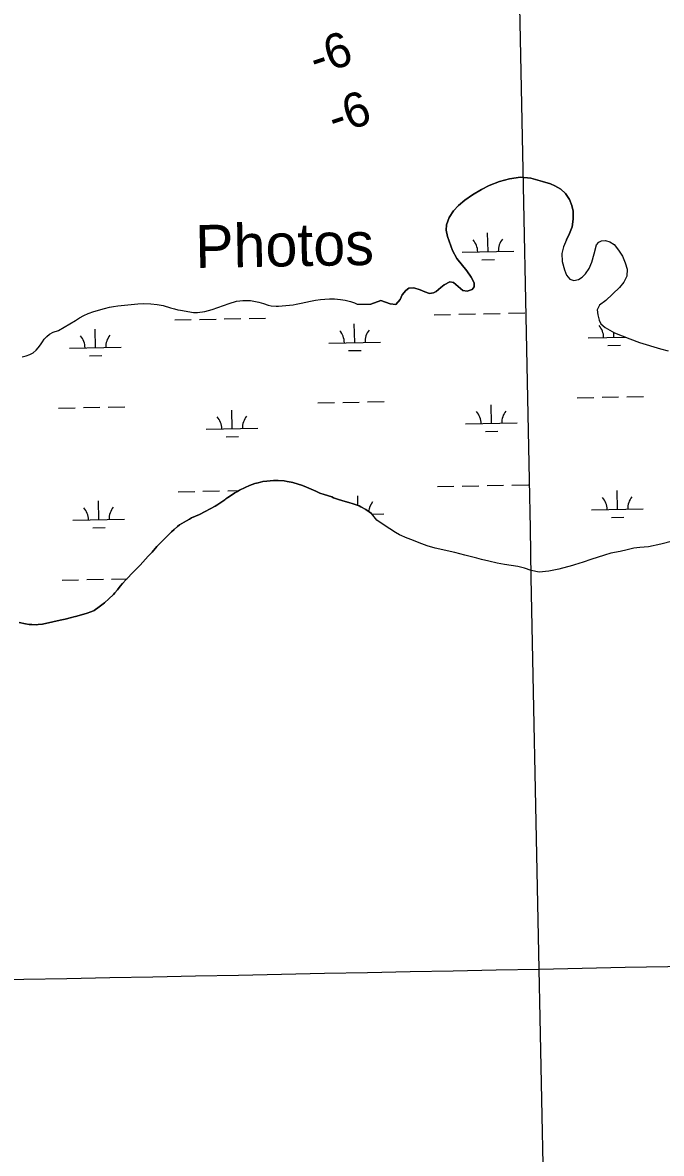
# Model space of a CAD drawing. Extents: x 3989314 to 4027622, y 243956 to 270014.
# Drawn here: x 4008451 to 4009687, y 255413 to 257601 of the extents above; entities that cross this region are included whole.
import ezdxf

# ---------------------------------------------------------------- set-up
doc = ezdxf.new("R2010")
doc.units = 0
for name, color, linetype in [('V-GRID-MAJR', 7, 'Continuous'), ('V-RIVR-EDGE', 7, 'Continuous'), ('V-RIVR-IDEN', 7, 'Continuous'), ('V-RIVR-RANG', 7, 'Continuous'), ('V-WETL-SWMP', 7, 'Continuous')]:
    doc.layers.add(name, color=color, linetype=linetype)

msp = doc.modelspace()

# ---------------------------------------------------------------- linework, layer by layer
at = {"layer": 'V-GRID-MAJR'}
for points in [[(4009571.406, 249713.95), (4009450.711, 255770.161), (4009329.948, 261829.84100000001), (4009209.185, 267889.513), (4009209.116, 267892.992)], [(3993497.629, 255455.714), (3998815.338, 255559.756), (4004133.032, 255664.571), (4009450.711, 255770.161), (4014768.3740000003, 255876.52300000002), (4020086.022, 255983.659), (4025403.6550000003, 256091.568)]]:
    msp.add_spline(points, degree=3, dxfattribs=at)
at = {"layer": 'V-RIVR-EDGE'}
for points in [[(4009503.705, 257181.21300000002), (4009509.585, 257193.147), (4009514.77, 257206.30800000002), (4009516.861, 257221.246), (4009516.791, 257236.722), (4009513.9390000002, 257247.679), (4009509.1610000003, 257258.931), (4009501.733, 257270.492), (4009493.0160000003, 257279.188), (4009480.853, 257285.557), (4009472.97, 257289.151), (4009457.146, 257294.169), (4009434.5870000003, 257300.573), (4009414.5700000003, 257302.557), (4009393.197, 257299.016), (4009373.724, 257294.21600000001), (4009353.932, 257286.522), (4009339.2090000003, 257278.45), (4009321.523, 257268.04), (4009307.23, 257258.026), (4009294.616, 257247.481), (4009285.159, 257237.335), (4009276.582, 257224.02300000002), (4009271.611, 257209.88700000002), (4009270.622, 257200), (4009273.43, 257187.351), (4009283.1040000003, 257160.252), (4009291.645, 257145.033), (4009310.5870000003, 257120.832), (4009319.211, 257108.753), (4009324.728, 257097.96600000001), (4009324.769, 257090.47100000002), (4009321.003, 257085.25), (4009311.4820000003, 257081.877), (4009303.294, 257083.063), (4009294.076, 257091.046), (4009284.8370000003, 257098.304), (4009278.105, 257099.695), (4009267.077, 257094.184), (4009260.64, 257088.552), (4009251.741, 257081.294), (4009246.113, 257078.785), (4009238.825, 257077.527), (4009229.2320000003, 257080.44400000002), (4009220.634, 257084.54200000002), (4009208.395, 257088.011), (4009198.717, 257087.786), (4009193.038, 257083.342), (4009185.792, 257074.58800000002), (4009181.923, 257065.503), (4009173.686, 257055.80800000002), (4009162.608, 257057.553), (4009144.1580000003, 257063.851), (4009125.109, 257056.861)], [(4009503.705, 257181.21300000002), (4009498.028, 257167.824), (4009494.782, 257154.854), (4009495.322, 257138.87900000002), (4009499.736, 257123.044), (4009503.568, 257112.544), (4009509.898, 257105.122), (4009517.813, 257102.734), (4009526.798, 257104.188), (4009533.935, 257108.833), (4009540.399, 257115.432), (4009547.684, 257125.63700000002), (4009552.609, 257138.078), (4009556.9, 257153.924), (4009561.966, 257171.682), (4009566.21, 257176.646), (4009571.115, 257179.176), (4009579.112, 257179.929), (4009587.755, 257177.52300000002), (4009595.828, 257171.987), (4009604.008, 257161.372), (4009611.915, 257149.555), (4009617.367, 257136.352), (4009620.918, 257124.408), (4009620.549, 257110.635), (4009614.69, 257099.429), (4009605.943, 257088.779), (4009579.8880000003, 257063.843), (4009567.3140000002, 257054.747), (4009562.72, 257045.681), (4009564.154, 257035.97100000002), (4009566.775, 257025.50400000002), (4009569.984, 257018.889), (4009578.483, 257011.168), (4009596.84, 257001.247), (4009626.028, 256989.58800000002), (4009645.185, 256982.549), (4009685.483, 256970.351), (4009700.3680000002, 256966.32700000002)], [(4008450.015, 256955.032), (4008458.166, 256956.839), (4008465.412, 256959.161), (4008471.492, 256962.26200000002), (4008477.448, 256967.691), (4008481.4620000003, 256972.215), (4008485.474, 256978.16400000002), (4008489.617, 256983.723), (4008493.115, 256988.767), (4008498.163, 256994.065), (4008503.341, 256998.331), (4008510.46, 257002.208), (4008520.421, 257005.823), (4008553.683, 257025.334), (4008561.06, 257030.24300000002), (4008569.7290000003, 257034.765), (4008578.271, 257038.511), (4008589.269, 257042.384), (4008609.7120000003, 257048.321), (4008619.415, 257050.643), (4008627.048, 257052.189), (4008635.199, 257053.478), (4008674.14, 257057.203), (4008685.654, 257057.842), (4008699.494, 257057.57200000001), (4008711.653, 257056.011), (4008723.167, 257053.803), (4008737.134, 257049.527), (4008745.023, 257047.321), (4008751.233, 257045.894), (4008756.535, 257045.114), (4008781.887, 257040.438), (4008789.907, 257040.692), (4008803.492, 257042.623), (4008817.723, 257046.494), (4008850.849, 257057.854), (4008865.339, 257062.24300000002), (4008871.4220000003, 257063.27300000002), (4008877.5, 257063.787), (4008885.004, 257064.03900000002), (4008892.119, 257063.519), (4008908.288, 257060.27300000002), (4008917.471, 257057.678), (4008926.394, 257054.82700000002), (4008932.473, 257053.4), (4008941.529, 257052.488), (4008946.573, 257052.484), (4008975.034, 257055.44), (4008980.469, 257056.859), (4008989.913, 257058.534), (4009008.543, 257062.661), (4009017.989, 257064.207), (4009027.563, 257065.622), (4009035.972, 257066.392), (4009045.287, 257066.904), (4009054.472, 257066.767), (4009066.242, 257065.725), (4009075.427, 257064.295), (4009085.644, 257061.831), (4009093.662, 257059.11000000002), (4009098.455, 257056.47), (4009125.109, 257056.861)], [(4008617.9220000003, 256486.325), (4008626.7290000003, 256494.73200000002), (4008629.319, 256498.22400000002), (4008634.501, 256504.173), (4008639.94, 256511.03), (4008644.6040000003, 256516.332), (4008651.858, 256523.834), (4008654.188, 256526.55000000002), (4008663.384, 256535.862), (4008669.472, 256542.58800000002), (4008672.1920000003, 256545.174), (4008678.539, 256551.771), (4008688.771, 256563.283), (4008694.21, 256569.23200000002), (4008696.412, 256571.301), (4008701.722, 256576.992), (4008710.92, 256587.47), (4008718.432, 256595.487), (4008721.9280000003, 256598.72100000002), (4008733.196, 256610.491), (4008739.154, 256616.312), (4008744.204, 256620.83800000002), (4008751.0670000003, 256626.65600000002), (4008754.694, 256629.372), (4008759.095, 256632.085), (4008768.157, 256637.256), (4008773.986, 256640.877), (4008778.258, 256643.204), (4008793.534, 256649.923), (4008804.409, 256655.22100000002), (4008823.572, 256665.951), (4008827.197, 256667.759), (4008834.836, 256672.543), (4008842.475, 256678.104), (4008844.677, 256680.172), (4008848.173, 256682.241), (4008853.612, 256685.991), (4008862.159, 256691.549), (4008867.207, 256694.394), (4008870.963, 256696.72), (4008881.7090000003, 256701.889), (4008889.9930000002, 256705.508), (4008900.739, 256709.51200000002), (4008906.821, 256711.189), (4008916.0130000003, 256713.256), (4008924.039, 256714.286), (4008936.4620000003, 256715.312), (4008945.393, 256715.693), (4008957.3000000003, 256714.65), (4008962.994, 256713.481)], [(4008962.994, 256713.481), (4008970.758, 256712.051), (4008973.994, 256711.27300000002), (4008992.755, 256705.69400000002), (4009000.259, 256702.71300000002), (4009018.634, 256694.934), (4009022.255, 256693.12), (4009026.654, 256691.176), (4009034.676, 256688.192), (4009049.686, 256683.525), (4009053.051, 256682.097), (4009062.367, 256678.726), (4009075.177, 256674.964), (4009082.423, 256673.019), (4009090.574, 256670.295), (4009094.844, 256669.256), (4009102.608, 256666.275), (4009105.715, 256664.718), (4009115.287, 256659.016), (4009126.037, 256651.627)], [(4009708.73, 256597.771), (4009686.21, 256592.084), (4009662.269, 256587.402), (4009645.787, 256585.907), (4009634.257, 256584.279), (4009621.233, 256581), (4009607.61, 256577.977), (4009589.631, 256574.708), (4009577.076, 256570.932), (4009550.739, 256562.566), (4009536.221, 256557.634), (4009519.028, 256552.168), (4009515.364, 256550.814), (4009488.826, 256544.025), (4009469.728, 256539.7), (4009451.059, 256537.779), (4009435.193, 256541.344), (4009422.133, 256545.682), (4009409.644, 256548.918), (4009383.399, 256553.123), (4009369.5670000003, 256555.787), (4009353.699, 256559.234), (4009339.166, 256562.885), (4009330.274, 256564.935), (4009306.736, 256570.883), (4009287.534, 256576.23), (4009249.308, 256584.50400000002), (4009233.832, 256589.026), (4009218.508, 256594.75400000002), (4009204.519, 256600.56900000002), (4009195.544, 256604.073), (4009180.481, 256610.52000000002), (4009172.973, 256614.587), (4009161.562, 256621.905), (4009152.522, 256627.465), (4009136.736, 256638.524), (4009126.037, 256651.627)], [(4008444.723, 256440.50100000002), (4008457.015, 256437.902), (4008463.616, 256436.99300000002), (4008468.92, 256436.6), (4008477.722, 256436.464), (4008481.216, 256436.98), (4008489.758, 256437.492), (4008509.823, 256441.748), (4008523.544, 256445.105), (4008533.77, 256447.16700000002), (4008545.679, 256450.266), (4008550.469, 256451.685), (4008553.705, 256452.33000000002), (4008574.288, 256458.269), (4008585.16, 256462.275), (4008589.435, 256464.084), (4008592.412, 256465.894), (4008596.684, 256468.739), (4008609.376, 256478.565), (4008617.9220000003, 256486.325)]]:
    msp.add_lwpolyline(points, dxfattribs=at)
at = {"layer": 'V-WETL-SWMP'}
for p, q in [((4009351.765940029, 257158.37311494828), (4009351.048637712, 257194.3659680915)), ((4009301.77586622, 257157.37686172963), (4009401.7560138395, 257159.36936816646)), ((4009340.0757859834, 257142.70607759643), (4009364.071021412, 257143.18427914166)), ((4008745.527214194, 257026.1965291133), (4008777.5208614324, 257026.83413117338)), ((4008793.517685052, 257027.15293220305), (4008825.5113322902, 257027.79053426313)), ((4008841.50815591, 257028.10933529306), (4008873.501803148, 257028.7469373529)), ((4008889.498626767, 257029.0657383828), (4008921.4922740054, 257029.70334044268)), ((4009247.3355735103, 257036.1970783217), (4009279.329220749, 257036.83468038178)), ((4009295.326044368, 257037.15348141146), (4009327.319691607, 257037.79108347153)), ((4009343.3165152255, 257038.10988450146), (4009375.310162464, 257038.7474865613)), ((4009391.3069860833, 257039.06628759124), (4009423.300633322, 257039.70388965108)), ((4008591.9769420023, 256972.38434705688), (4008591.2596396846, 257008.37720020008)), ((4009093.7853013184, 256982.38489626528), (4009093.0679990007, 257018.37774940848)), ((4009595.593660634, 256992.3854454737), (4009595.401576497, 257002.02385868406)), ((4009043.7952275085, 256981.38864304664), (4009143.7753751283, 256983.38114948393)), ((4009545.6035868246, 256991.38919225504), (4009617.9109418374, 256992.83020703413)), ((4009583.903506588, 256976.71840812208), (4009607.898742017, 256977.19660966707)), ((4008541.9868681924, 256971.3880938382), (4008641.967015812, 256973.38060027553)), ((4008580.2867879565, 256956.71730970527), (4008604.2820233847, 256957.19551125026)), ((4009082.095147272, 256966.71785891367), (4009106.090382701, 256967.19606045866)), ((4009022.691864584, 256865.51315313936), (4009054.685511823, 256866.1507551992)), ((4009070.6823354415, 256866.46955622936), (4009102.6759826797, 256867.10715828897)), ((4009118.6728062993, 256867.4259593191), (4009150.6664535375, 256868.06356137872)), ((4009524.5002238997, 256875.51370234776), (4009556.4938711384, 256876.1513044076)), ((4009572.4906947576, 256876.47010543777), (4009604.4843419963, 256877.10770749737)), ((4009620.4811656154, 256877.4265085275), (4009652.474812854, 256878.06411058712)), ((4008520.883505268, 256855.51260393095), (4008552.8771525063, 256856.1502059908)), ((4008568.873976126, 256856.46900702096), (4008600.8676233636, 256857.10660908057)), ((4008616.8644469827, 256857.4254101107), (4008648.858094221, 256858.0630121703)), ((4008856.586151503, 256815.76360964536), (4008855.868849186, 256851.7564627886)), ((4009358.3945108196, 256825.76415885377), (4009357.677208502, 256861.757011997)), ((4009308.4044370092, 256824.76790563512), (4009408.384584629, 256826.76041207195)), ((4008806.596077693, 256814.76735642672), (4008906.5762253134, 256816.75986286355)), ((4008844.895997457, 256800.09657229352), (4008868.8912328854, 256800.57477383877)), ((4009346.7043567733, 256810.09712150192), (4009370.6995922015, 256810.57532304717)), ((4008752.155784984, 256693.5875730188), (4008784.1494322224, 256694.22517507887)), ((4008800.146255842, 256694.54397610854), (4008832.13990308, 256695.18157816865)), ((4008848.136726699, 256695.50037919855), (4008869.6869692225, 256695.929854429)), ((4009253.9641443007, 256703.5881222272), (4009285.9577915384, 256704.22572428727)), ((4009301.954615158, 256704.54452531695), (4009333.948262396, 256705.18212737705)), ((4009349.9450860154, 256705.50092840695), (4009381.9387332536, 256706.1385304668)), ((4009397.9355568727, 256706.45733149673), (4009429.929204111, 256707.09493355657)), ((4009602.2222314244, 256659.77648937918), (4009601.5049291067, 256695.7693425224)), ((4008598.605512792, 256639.77539096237), (4008597.8882104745, 256675.7682441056)), ((4009100.0656191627, 256667.2506043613), (4009099.696569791, 256685.768793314)), ((4009127.1156538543, 256650.30808053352), (4009150.403945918, 256650.77219338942)), ((4009552.232157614, 256658.78023616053), (4009652.212305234, 256660.77274259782)), ((4008548.615438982, 256638.77913774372), (4008648.595586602, 256640.77164418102)), ((4009590.532077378, 256644.10945202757), (4009614.527312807, 256644.58765357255)), ((4008586.9153587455, 256624.10835361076), (4008610.9105941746, 256624.58655515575)), ((4008527.5120760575, 256522.90364783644), (4008559.505723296, 256523.54124989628)), ((4008575.5025469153, 256523.86005092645), (4008607.4961941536, 256524.49765298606)), ((4008623.4930177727, 256524.81645401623), (4008653.2090320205, 256525.4086650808))]:
    msp.add_line(p, q, dxfattribs=at)
for points in [[(4008751.2320000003, 257045.894), (4008756.535, 257045.114), (4008781.887, 257040.439), (4008789.907, 257040.692), (4008803.492, 257042.623), (4008817.724, 257046.494), (4008850.849, 257057.855), (4008865.34, 257062.24300000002), (4008871.421, 257063.274), (4008877.501, 257063.787), (4008885.005, 257064.04), (4008892.119, 257063.518), (4008908.287, 257060.27300000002), (4008917.47, 257057.679), (4008926.394, 257054.82700000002), (4008932.473, 257053.4), (4008941.528, 257052.488), (4008946.573, 257052.484), (4008975.035, 257055.44), (4008980.469, 257056.859), (4008989.913, 257058.534), (4009008.544, 257062.661), (4009017.989, 257064.207), (4009027.563, 257065.623), (4009035.972, 257066.393), (4009045.2860000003, 257066.904), (4009054.471, 257066.768), (4009066.242, 257065.725), (4009075.426, 257064.296), (4009085.644, 257061.831), (4009093.662, 257059.109), (4009098.454, 257056.469), (4009125.11, 257056.861), (4009144.157, 257063.85), (4009162.608, 257057.554), (4009173.685, 257055.80800000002), (4009181.923, 257065.503), (4009185.792, 257074.58800000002), (4009193.037, 257083.342), (4009198.717, 257087.785), (4009208.395, 257088.01), (4009220.6350000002, 257084.541), (4009229.231, 257080.443), (4009238.825, 257077.527), (4009246.113, 257078.784), (4009251.741, 257081.294), (4009260.64, 257088.552), (4009267.077, 257094.184), (4009278.105, 257099.69400000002), (4009284.838, 257098.305), (4009294.075, 257091.047), (4009303.293, 257083.063), (4009311.4820000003, 257081.878), (4009321.003, 257085.25100000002), (4009324.769, 257090.47), (4009324.727, 257097.967), (4009319.211, 257108.75400000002), (4009310.586, 257120.832), (4009291.645, 257145.034), (4009283.1040000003, 257160.253), (4009273.429, 257187.351), (4009270.622, 257200), (4009271.611, 257209.888), (4009276.582, 257224.022), (4009285.1580000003, 257237.334), (4009294.617, 257247.48), (4009307.23, 257258.025), (4009321.522, 257268.041), (4009339.2090000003, 257278.451), (4009353.933, 257286.522), (4009373.724, 257294.21600000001), (4009393.196, 257299.016), (4009414.569, 257302.557), (4009434.586, 257300.573), (4009457.145, 257294.168), (4009472.971, 257289.152), (4009480.8540000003, 257285.557), (4009493.017, 257279.188), (4009501.7320000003, 257270.492), (4009509.1610000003, 257258.93), (4009513.9390000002, 257247.679), (4009516.791, 257236.722), (4009516.862, 257221.245), (4009514.771, 257206.30800000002), (4009509.5840000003, 257193.147), (4009503.705, 257181.214), (4009498.028, 257167.824), (4009494.781, 257154.853), (4009495.322, 257138.88), (4009499.736, 257123.045), (4009503.5670000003, 257112.545), (4009509.898, 257105.122), (4009517.8140000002, 257102.73500000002), (4009526.799, 257104.188), (4009533.935, 257108.834), (4009540.398, 257115.432), (4009547.683, 257125.636), (4009552.608, 257138.078), (4009556.9, 257153.923), (4009561.967, 257171.682), (4009566.21, 257176.646)], [(4009566.21, 257176.646), (4009571.114, 257179.176), (4009579.113, 257179.93), (4009587.754, 257177.52300000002), (4009595.828, 257171.988), (4009604.008, 257161.373), (4009611.915, 257149.555), (4009617.366, 257136.352), (4009620.917, 257124.409), (4009620.549, 257110.636), (4009614.6890000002, 257099.428), (4009605.9420000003, 257088.78), (4009579.8880000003, 257063.843), (4009567.3140000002, 257054.748), (4009562.72, 257045.681), (4009564.153, 257035.97100000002), (4009566.776, 257025.50400000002), (4009569.985, 257018.889), (4009578.484, 257011.16700000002), (4009596.839, 257001.247), (4009626.028, 256989.58800000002), (4009645.185, 256982.549), (4009685.483, 256970.352), (4009700.3680000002, 256966.328)], [(4008450.014, 256955.033), (4008458.165, 256956.83800000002), (4008465.4110000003, 256959.162), (4008471.4930000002, 256962.26200000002), (4008477.447, 256967.691), (4008481.461, 256972.21600000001), (4008485.475, 256978.16400000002), (4008489.6180000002, 256983.723), (4008493.115, 256988.766), (4008498.163, 256994.066), (4008503.341, 256998.332), (4008510.4590000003, 257002.208), (4008520.4220000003, 257005.823), (4008553.682, 257025.333), (4008561.059, 257030.244), (4008569.7290000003, 257034.766), (4008578.27, 257038.511), (4008589.268, 257042.384), (4008609.711, 257048.321), (4008619.415, 257050.643), (4008627.049, 257052.19), (4008635.199, 257053.477), (4008674.14, 257057.20200000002), (4008685.653, 257057.84100000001), (4008699.495, 257057.57200000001), (4008711.654, 257056.011), (4008723.166, 257053.804), (4008737.134, 257049.526), (4008745.023, 257047.321), (4008751.2320000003, 257045.894)], [(4008957.3000000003, 256714.65), (4008945.394, 256715.693), (4008936.463, 256715.31100000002), (4008924.038, 256714.285), (4008916.0130000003, 256713.255), (4008906.822, 256711.19), (4008900.738, 256709.51200000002), (4008889.9930000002, 256705.508), (4008881.708, 256701.889), (4008870.9620000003, 256696.72), (4008867.207, 256694.393), (4008862.1580000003, 256691.549), (4008853.612, 256685.99000000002), (4008848.173, 256682.24000000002), (4008844.677, 256680.172), (4008842.4760000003, 256678.103), (4008834.836, 256672.543), (4008827.197, 256667.76), (4008823.572, 256665.95), (4008804.409, 256655.222), (4008793.534, 256649.923), (4008778.258, 256643.203), (4008773.985, 256640.877), (4008768.1580000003, 256637.257), (4008759.095, 256632.086), (4008754.693, 256629.371), (4008751.0670000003, 256626.65600000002), (4008744.204, 256620.837), (4008739.153, 256616.31100000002), (4008733.1950000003, 256610.491), (4008721.927, 256598.72100000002), (4008718.431, 256595.488), (4008710.919, 256587.469), (4008701.722, 256576.992), (4008696.412, 256571.301), (4008694.21, 256569.23200000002), (4008688.77, 256563.282), (4008678.538, 256551.771), (4008672.1920000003, 256545.174), (4008669.472, 256542.58800000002), (4008663.384, 256535.862), (4008654.1890000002, 256526.55000000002), (4008651.8570000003, 256523.834), (4008644.6040000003, 256516.332), (4008639.941, 256511.029), (4008634.501, 256504.173), (4008629.3200000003, 256498.22400000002), (4008626.7290000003, 256494.731), (4008617.9220000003, 256486.325), (4008609.375, 256478.565), (4008596.685, 256468.738), (4008592.412, 256465.894), (4008589.434, 256464.084), (4008585.1610000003, 256462.275), (4008574.287, 256458.27000000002), (4008553.705, 256452.331), (4008550.469, 256451.68600000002), (4008545.679, 256450.266), (4008533.77, 256447.168), (4008523.544, 256445.104), (4008509.823, 256441.749), (4008489.759, 256437.492), (4008481.217, 256436.98), (4008477.722, 256436.465), (4008468.921, 256436.6), (4008463.615, 256436.992), (4008457.015, 256437.903), (4008444.722, 256440.5)], [(4009708.73, 256597.77000000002), (4009686.211, 256592.083), (4009662.269, 256587.401), (4009645.7860000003, 256585.90600000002), (4009634.257, 256584.279), (4009621.233, 256580.999), (4009607.611, 256577.977), (4009589.63, 256574.708), (4009577.077, 256570.932), (4009550.739, 256562.566), (4009536.22, 256557.634), (4009519.0270000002, 256552.168), (4009515.364, 256550.814), (4009488.826, 256544.026), (4009469.7290000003, 256539.699), (4009451.059, 256537.778), (4009435.194, 256541.344), (4009422.132, 256545.682), (4009409.644, 256548.91700000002), (4009383.399, 256553.123), (4009369.566, 256555.788), (4009353.699, 256559.234), (4009339.167, 256562.886), (4009330.275, 256564.93600000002), (4009306.737, 256570.883), (4009287.535, 256576.231), (4009249.308, 256584.50400000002), (4009233.832, 256589.027), (4009218.509, 256594.755), (4009204.518, 256600.56900000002), (4009195.544, 256604.07200000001), (4009180.4820000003, 256610.519), (4009172.974, 256614.58800000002), (4009161.562, 256621.905), (4009152.522, 256627.465), (4009136.736, 256638.525), (4009126.038, 256651.628), (4009115.287, 256659.017), (4009105.714, 256664.718), (4009102.608, 256666.274), (4009094.845, 256669.256), (4009090.575, 256670.294), (4009082.423, 256673.018), (4009075.177, 256674.964), (4009062.366, 256678.726), (4009053.0500000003, 256682.098), (4009049.686, 256683.524), (4009034.676, 256688.193), (4009026.654, 256691.176), (4009022.255, 256693.12), (4009018.633, 256694.935), (4009000.2600000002, 256702.71300000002), (4008992.756, 256705.695), (4008973.9930000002, 256711.27300000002), (4008970.758, 256712.052), (4008962.994, 256713.481), (4008957.3000000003, 256714.65)]]:
    msp.add_lwpolyline(points, dxfattribs=at)
for centre, radius, start, end in [((4009296.52451048, 257157.74710481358), 35.24628790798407, 0.3698775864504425, 41.913535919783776), ((4009406.98844861, 257159.94854292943), 35.246287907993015, 140.36987458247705, 181.91353291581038), ((4009038.5438717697, 256981.75888613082), 35.24628790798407, 0.3698775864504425, 41.913535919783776), ((4009149.007809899, 256983.9603242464), 35.246287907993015, 140.36987458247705, 181.91353291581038), ((4009540.3522310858, 256991.75943533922), 35.24628790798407, 0.3698775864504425, 41.913535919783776), ((4008536.735512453, 256971.75833692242), 35.24628790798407, 0.3698775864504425, 41.913535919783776), ((4008647.1994505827, 256973.959775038), 35.246287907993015, 140.36987458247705, 181.91353291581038), ((4009650.8161692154, 256993.9608734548), 35.246287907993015, 180.31827590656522, 181.91353291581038), ((4009303.1530812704, 256825.13814871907), 35.24628790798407, 0.3698775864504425, 41.913535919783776), ((4009413.6170193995, 256827.33958683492), 35.246287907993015, 140.36987458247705, 181.91353291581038), ((4008801.344721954, 256815.13759951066), 35.24628790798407, 0.3698775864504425, 41.913535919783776), ((4008911.808660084, 256817.33903762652), 35.246287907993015, 140.36987458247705, 181.91353291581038), ((4009155.6363806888, 256651.3513681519), 35.246287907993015, 140.36987458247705, 173.48081828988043), ((4009546.9808018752, 256659.1504792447), 35.24628790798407, 0.3698775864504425, 41.913535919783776), ((4009657.444740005, 256661.3519173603), 35.246287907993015, 140.36987458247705, 181.91353291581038), ((4008543.3640832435, 256639.1493808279), 35.24628790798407, 0.3698775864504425, 41.913535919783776), ((4008653.8280213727, 256641.3508189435), 35.246287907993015, 140.36987458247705, 181.91353291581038)]:
    msp.add_arc(centre, radius, start, end, dxfattribs=at)

# ---------------------------------------------------------------- texts
at = {"layer": 'V-RIVR-IDEN'}
msp.add_text('Photos', height=82.999832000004, rotation=1.009144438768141, dxfattribs=at).set_placement((4008786.0255158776, 257126.6336528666))
at = {"layer": 'V-RIVR-RANG'}
for p in [(4009019.0417494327, 257498.1136418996), (4009055.0617494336, 257383.2836418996)]:
    msp.add_text('-6', height=67, rotation=18.62047222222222, dxfattribs=at).set_placement(p)

doc.saveas('drawing.dxf')
